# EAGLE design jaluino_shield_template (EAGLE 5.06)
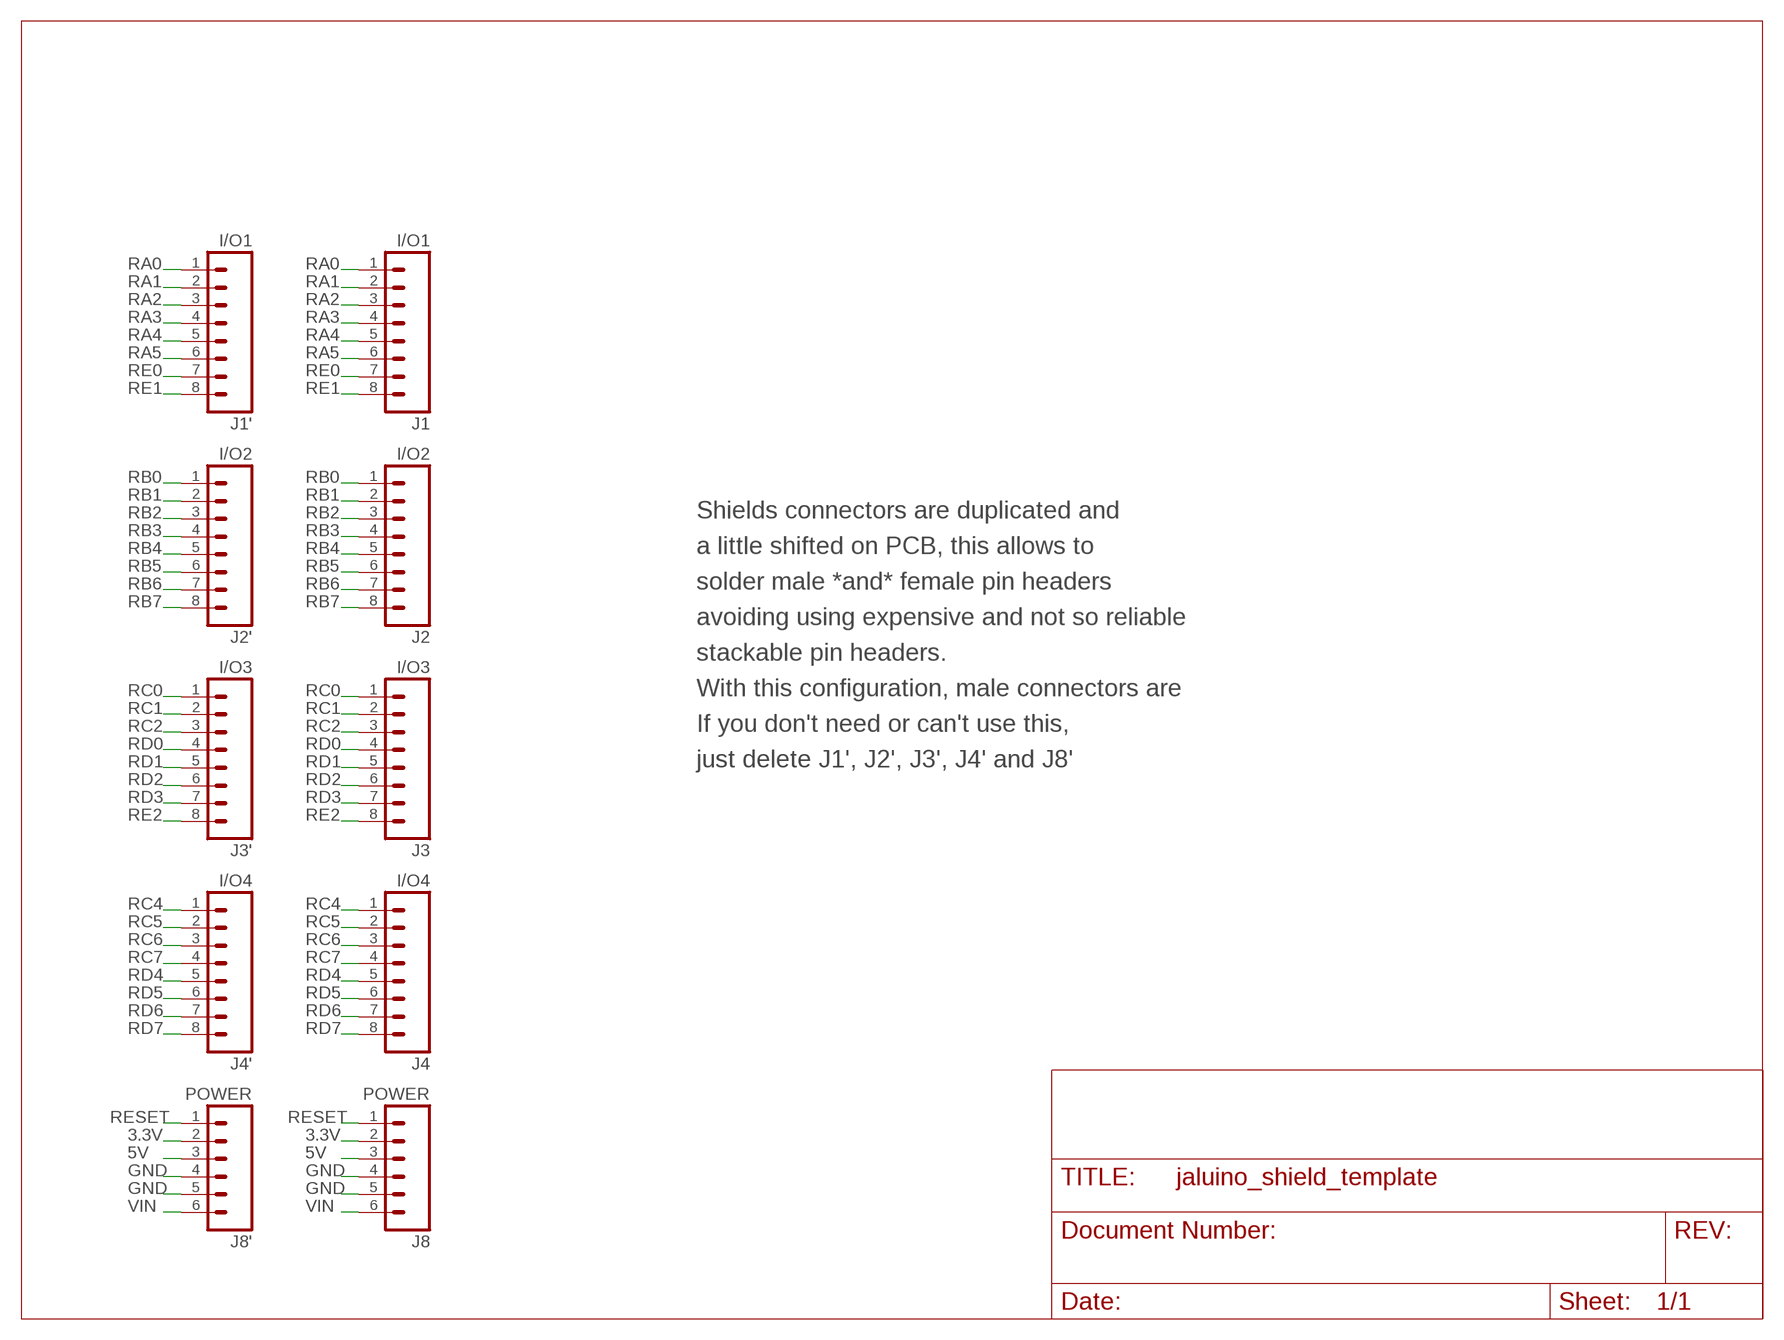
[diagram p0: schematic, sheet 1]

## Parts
J1  I/O1  M08  [1X08]
J1'  I/O1  M08  [1X08]
J2  I/O2  M08  [1X08]
J2'  I/O2  M08  [1X08]
J3  I/O3  M08  [1X08]
J3'  I/O3  M08  [1X08]
J4  I/O4  M08  [1X08]
J4'  I/O4  M08  [1X08]
J8  POWER  M06SIP  [1X06]
J8'  POWER  M06SIP  [1X06]

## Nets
3.3V: J8'.2 J8.2
5V: J8'.3 J8.3
GND: J8'.4 J8'.5 J8.4 J8.5
RA0: J1'.1 J1.1
RA1: J1'.2 J1.2
RA2: J1'.3 J1.3
RA3: J1'.4 J1.4
RA4: J1'.5 J1.5
RA5: J1'.6 J1.6
RB0: J2'.1 J2.1
RB1: J2'.2 J2.2
RB2: J2'.3 J2.3
RB3: J2'.4 J2.4
RB4: J2'.5 J2.5
RB5: J2'.6 J2.6
RB6: J2'.7 J2.7
RB7: J2'.8 J2.8
RC0: J3'.1 J3.1
RC1: J3'.2 J3.2
RC2: J3'.3 J3.3
RC4: J4'.1 J4.1
RC5: J4'.2 J4.2
RC6: J4'.3 J4.3
RC7: J4'.4 J4.4
RD0: J3'.4 J3.4
RD1: J3'.5 J3.5
RD2: J3'.6 J3.6
RD3: J3'.7 J3.7
RD4: J4'.5 J4.5
RD5: J4'.6 J4.6
RD6: J4'.7 J4.7
RD7: J4'.8 J4.8
RE0: J1'.7 J1.7
RE1: J1'.8 J1.8
RE2: J3'.8 J3.8
RESET: J8'.1 J8.1
VIN: J8'.6 J8.6

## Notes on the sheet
- Shields connectors are duplicated and
- a little shifted on PCB, this allows to
- solder male *and* female pin headers
- avoiding using expensive and not so reliable
- stackable pin headers.
- With this configuration, male connectors are
- If you don't need or can't use this,
- just delete J1', J2', J3', J4' and J8'

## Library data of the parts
J1 J1' J2 J2' J3 J3' J4 J4' = SparkFun:M08: Header 8 Standard 8-pin 0.1" header. Use with straight break away headers (SKU : PRT-00116), right angle break away headers (PRT-00553), swiss pins (PRT-00743), machine pins (PRT-00117), and female headers (PRT-00115).
J8 J8' = SparkFun:M06: Header 6 Standard 6-pin 0.1" header. Use with straight break away headers (SKU : PRT-00116), right angle break away headers (PRT-00553), swiss pins (PRT-00743), machine pins (PRT-00117), and female headers (PRT-00115). Molex polarized connector foot print use with SKU : PRT-08094 with associated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

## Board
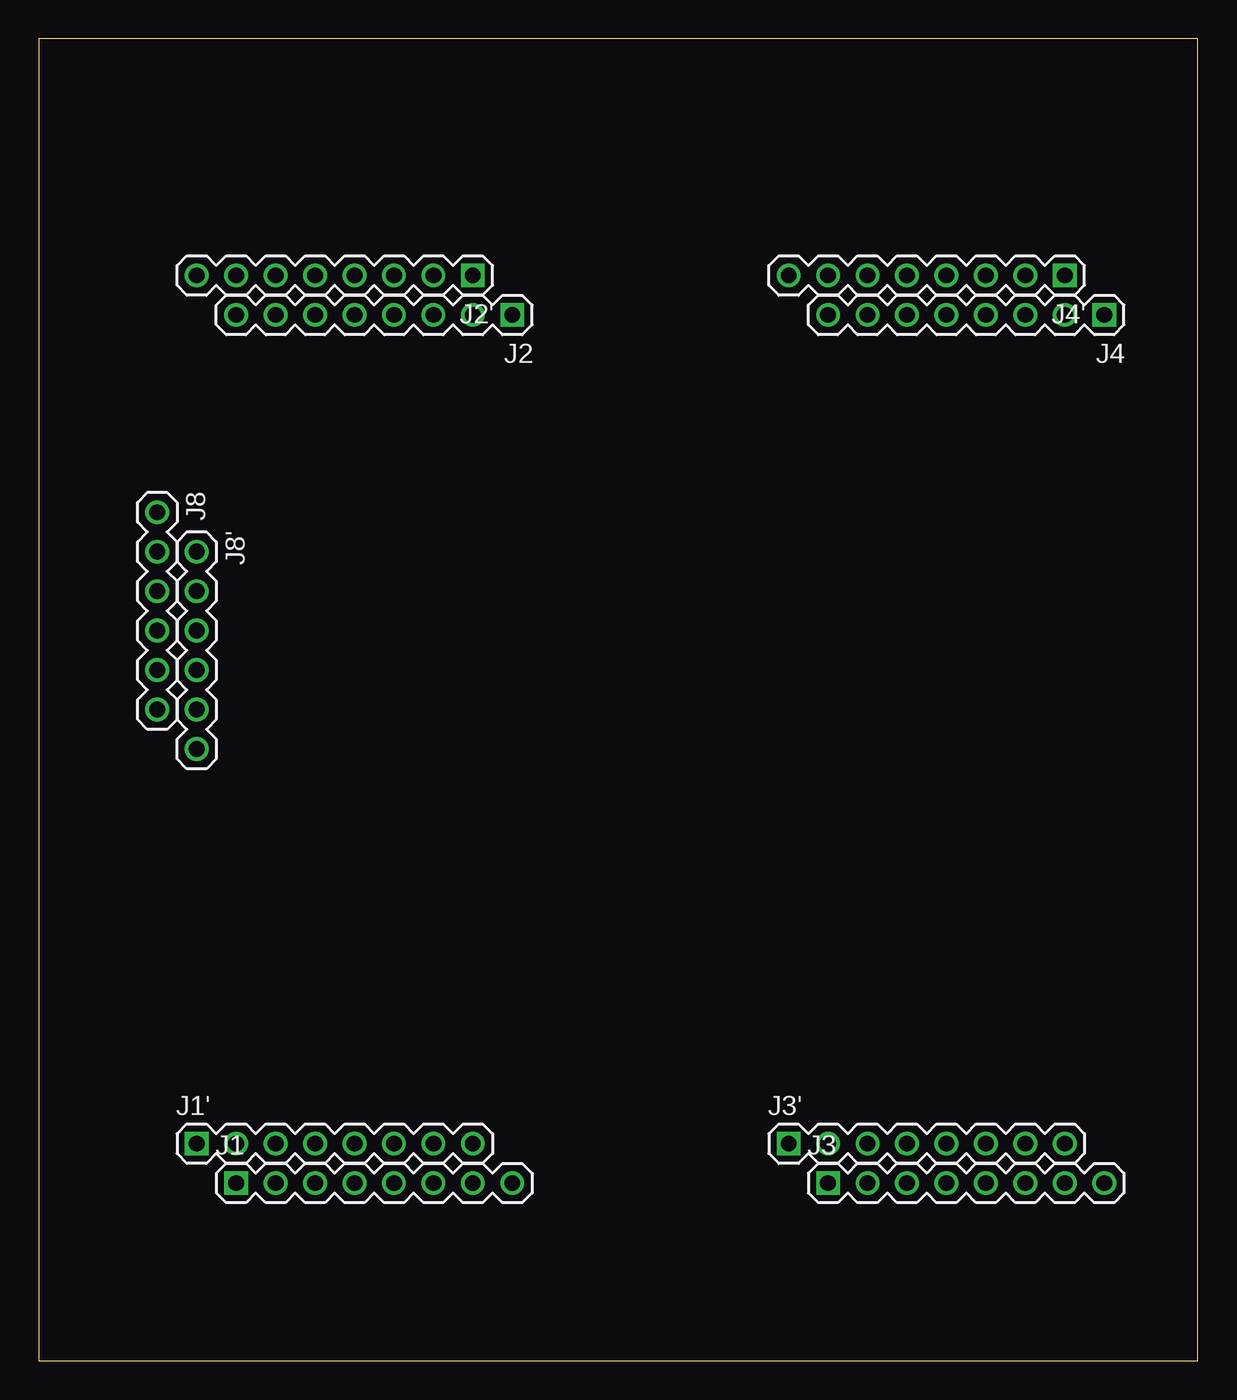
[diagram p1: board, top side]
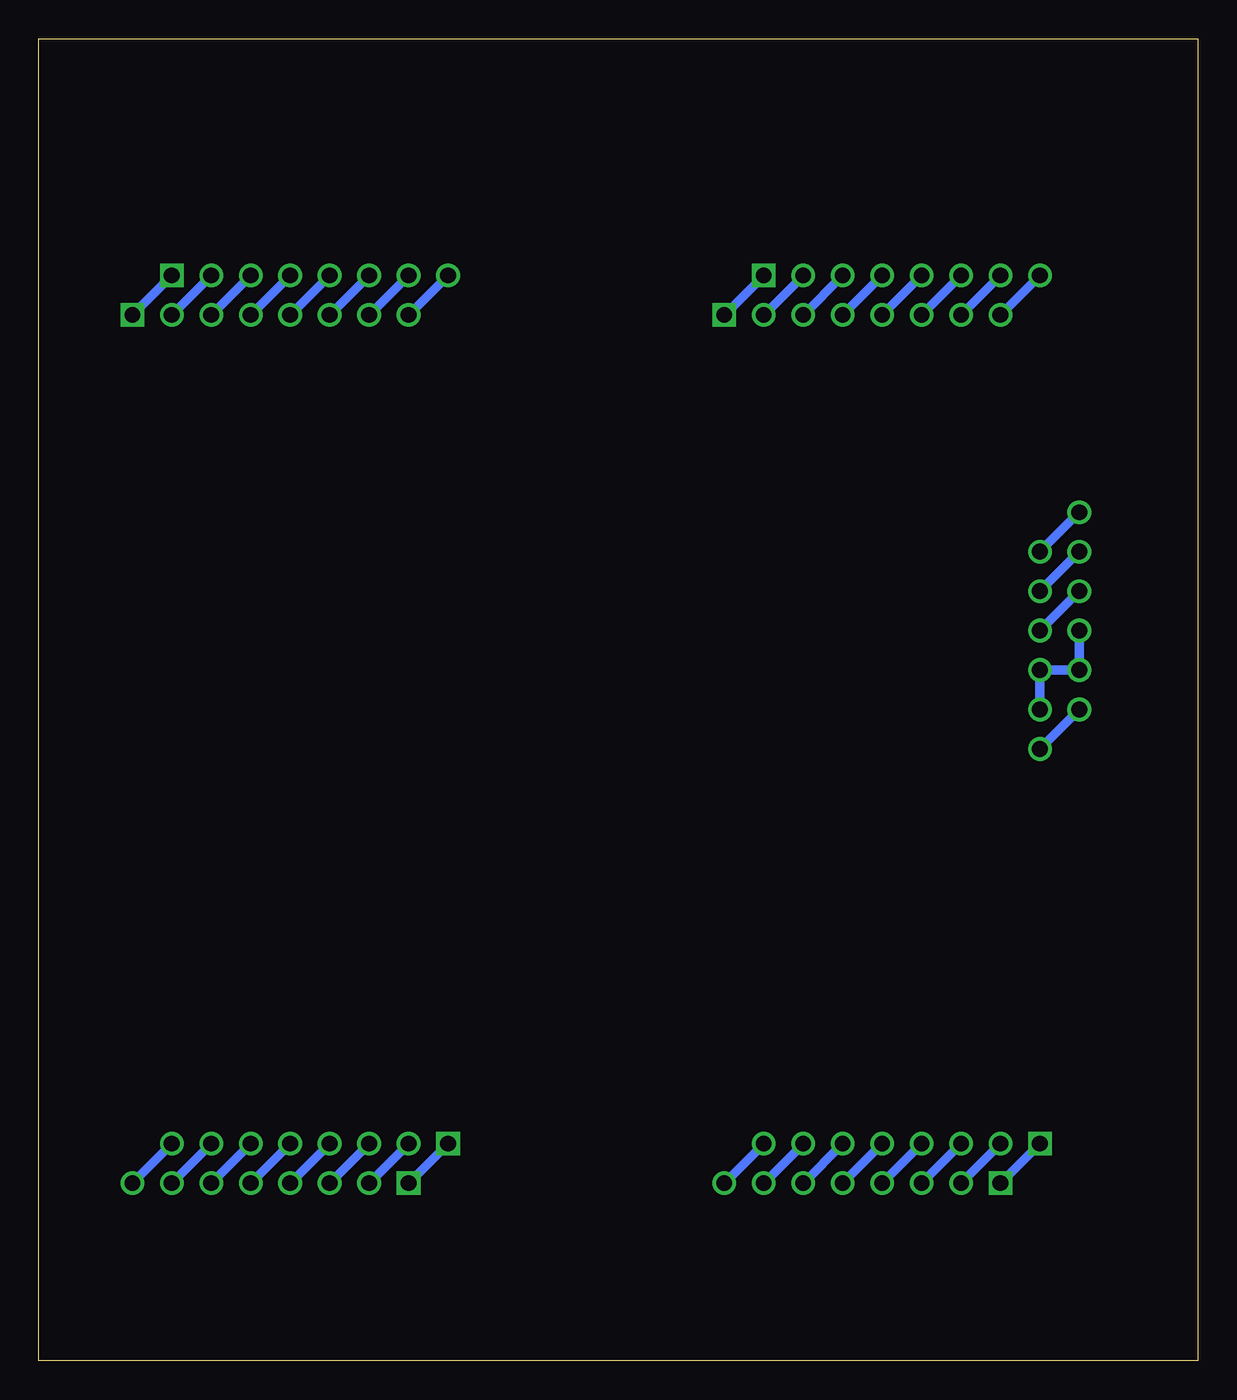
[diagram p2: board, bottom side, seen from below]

Size 74.6 x 85.08 mm. Coordinates in mm from the lower left corner, seen from the top.
Outline: 0,0 74.6,0 74.6,85.08 0,85.08 0,0
Copper layers (1*16): Top 0.035mm / dielectric 1.5mm / Bottom 0.035mm
Design rules "cuckoo": minimum track width 6mil, minimum drill 12mil, track to track 6mil, track to pad 6mil, pad to pad 6mil, via to via 6mil, smd to smd 0mil, copper to edge 10mil, drill to drill 10mil, minimum pad ring 10mil, minimum via ring 6mil, stop-mask expansion 2mil, vias tented up to drill 100mil, thermal gap 10mil

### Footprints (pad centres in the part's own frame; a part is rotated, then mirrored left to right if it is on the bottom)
1X08 = drill 1.016 square: 1 0,0 | drill 1.016 round: 2 2.54,0; 3 5.08,0; 4 7.62,0; 5 10.16,0; 6 12.7,0; 7 15.24,0; 8 17.78,0
1X06 = drill 1.016 round: 1 0,0; 2 2.54,0; 3 5.08,0; 4 7.62,0; 5 10.16,0; 6 12.7,0

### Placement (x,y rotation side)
J1  12.7,11.43 0 top
J1'  10.16,13.97 0 top
J2  30.48,67.31 180 top
J2'  27.94,69.85 180 top
J3  50.8,11.43 0 top
J3'  48.26,13.97 0 top
J4  68.58,67.31 180 top
J4'  66.04,69.85 180 top
J8  7.62,54.61 270 top
J8'  10.16,52.07 270 top

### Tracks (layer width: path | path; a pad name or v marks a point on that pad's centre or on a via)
3.3V
  Bottom 0.61: J8.2 J8'.2
5V
  Bottom 0.61: J8.3 J8'.3
GND
  Bottom 0.61: J8.4 J8.5 J8'.4 J8'.5
RA0
  Bottom 0.61: J1.1 J1'.1
RA1
  Bottom 0.61: J1.2 J1'.2
RA2
  Bottom 0.61: J1'.3 J1.3
RA3
  Bottom 0.61: J1'.4 J1.4
RA4
  Bottom 0.61: J1'.5 J1.5
RA5
  Bottom 0.61: J1'.6 J1.6
RB0
  Bottom 0.61: J2.1 J2'.1
RB1
  Bottom 0.61: J2.2 J2'.2
RB2
  Bottom 0.61: J2.3 J2'.3
RB3
  Bottom 0.61: J2.4 J2'.4
RB4
  Bottom 0.61: J2.5 J2'.5
RB5
  Bottom 0.61: J2.6 J2'.6
RB6
  Bottom 0.61: J2.7 J2'.7
RB7
  Bottom 0.61: J2.8 J2'.8
RC0
  Bottom 0.61: J3'.1 J3.1
RC1
  Bottom 0.61: J3'.2 J3.2
RC2
  Bottom 0.61: J3'.3 J3.3
RC4
  Bottom 0.61: J4'.1 J4.1
RC5
  Bottom 0.61: J4'.2 J4.2
RC6
  Bottom 0.61: J4'.3 J4.3
RC7
  Bottom 0.61: J4'.4 J4.4
RD0
  Bottom 0.61: J3'.4 J3.4
RD1
  Bottom 0.61: J3'.5 J3.5
RD2
  Bottom 0.61: J3'.6 J3.6
RD3
  Bottom 0.61: J3'.7 J3.7
RD4
  Bottom 0.61: J4'.5 J4.5
RD5
  Bottom 0.61: J4'.6 J4.6
RD6
  Bottom 0.61: J4'.7 J4.7
RD7
  Bottom 0.61: J4'.8 J4.8
RE0
  Bottom 0.61: J1'.7 J1.7
RE1
  Bottom 0.61: J1'.8 J1.8
RE2
  Bottom 0.61: J3'.8 J3.8
RESET
  Bottom 0.61: J8.1 J8'.1
VIN
  Bottom 0.61: J8.6 J8'.6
